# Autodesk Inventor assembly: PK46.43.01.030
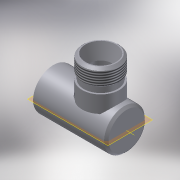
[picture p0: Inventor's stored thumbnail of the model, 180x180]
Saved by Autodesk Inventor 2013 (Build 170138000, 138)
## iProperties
Shininess: 64.0
Length Units: 11269
Angle Units: 11279
Time Units: 11290
Mass Units: 11283
Length Display Precision: 3
Angle Display Precision: 2
Compacted: True
Created: 2004-12
Part Number: PK46.43.01.030
Document SubType Name: Assembly
Designer: ELarisa
Manufacturer: Standard
Standards Organization: Custom
Density: 0.0
Volumn: 0.0
Area: 0.0
PropertySet Name: Model Information
Control State: 0
Master: False
Checked Out: False
Checked Out Date: 2008-10-09
Last Check In Date: 2008-10-09
Author: ELarisa
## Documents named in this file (3)
- C:\Product Design Suite 2013 Test Drive\Dynamic Simulation\Workspace\Assy, Chassis, Front\PK46.43.01.030.iam
- C:\Product Design Suite 2013 Test Drive\Dynamic Simulation\Workspace\Assy, Chassis, Front\PK46.43.01.031.ipt
- C:\Product Design Suite 2013 Test Drive\Dynamic Simulation\Workspace\Assy, Chassis, Front\027.03.02.007.ipt
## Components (2 placed, 2 different names)
1. PK46.43.01.031:1 — Вставка:1
2. 027.03.02.007:1 — Вставка:1
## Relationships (1: Insert 1)
- Вставка:1 [Insert]: PK46.43.01.031:1 ↔ 027.03.02.007:1
